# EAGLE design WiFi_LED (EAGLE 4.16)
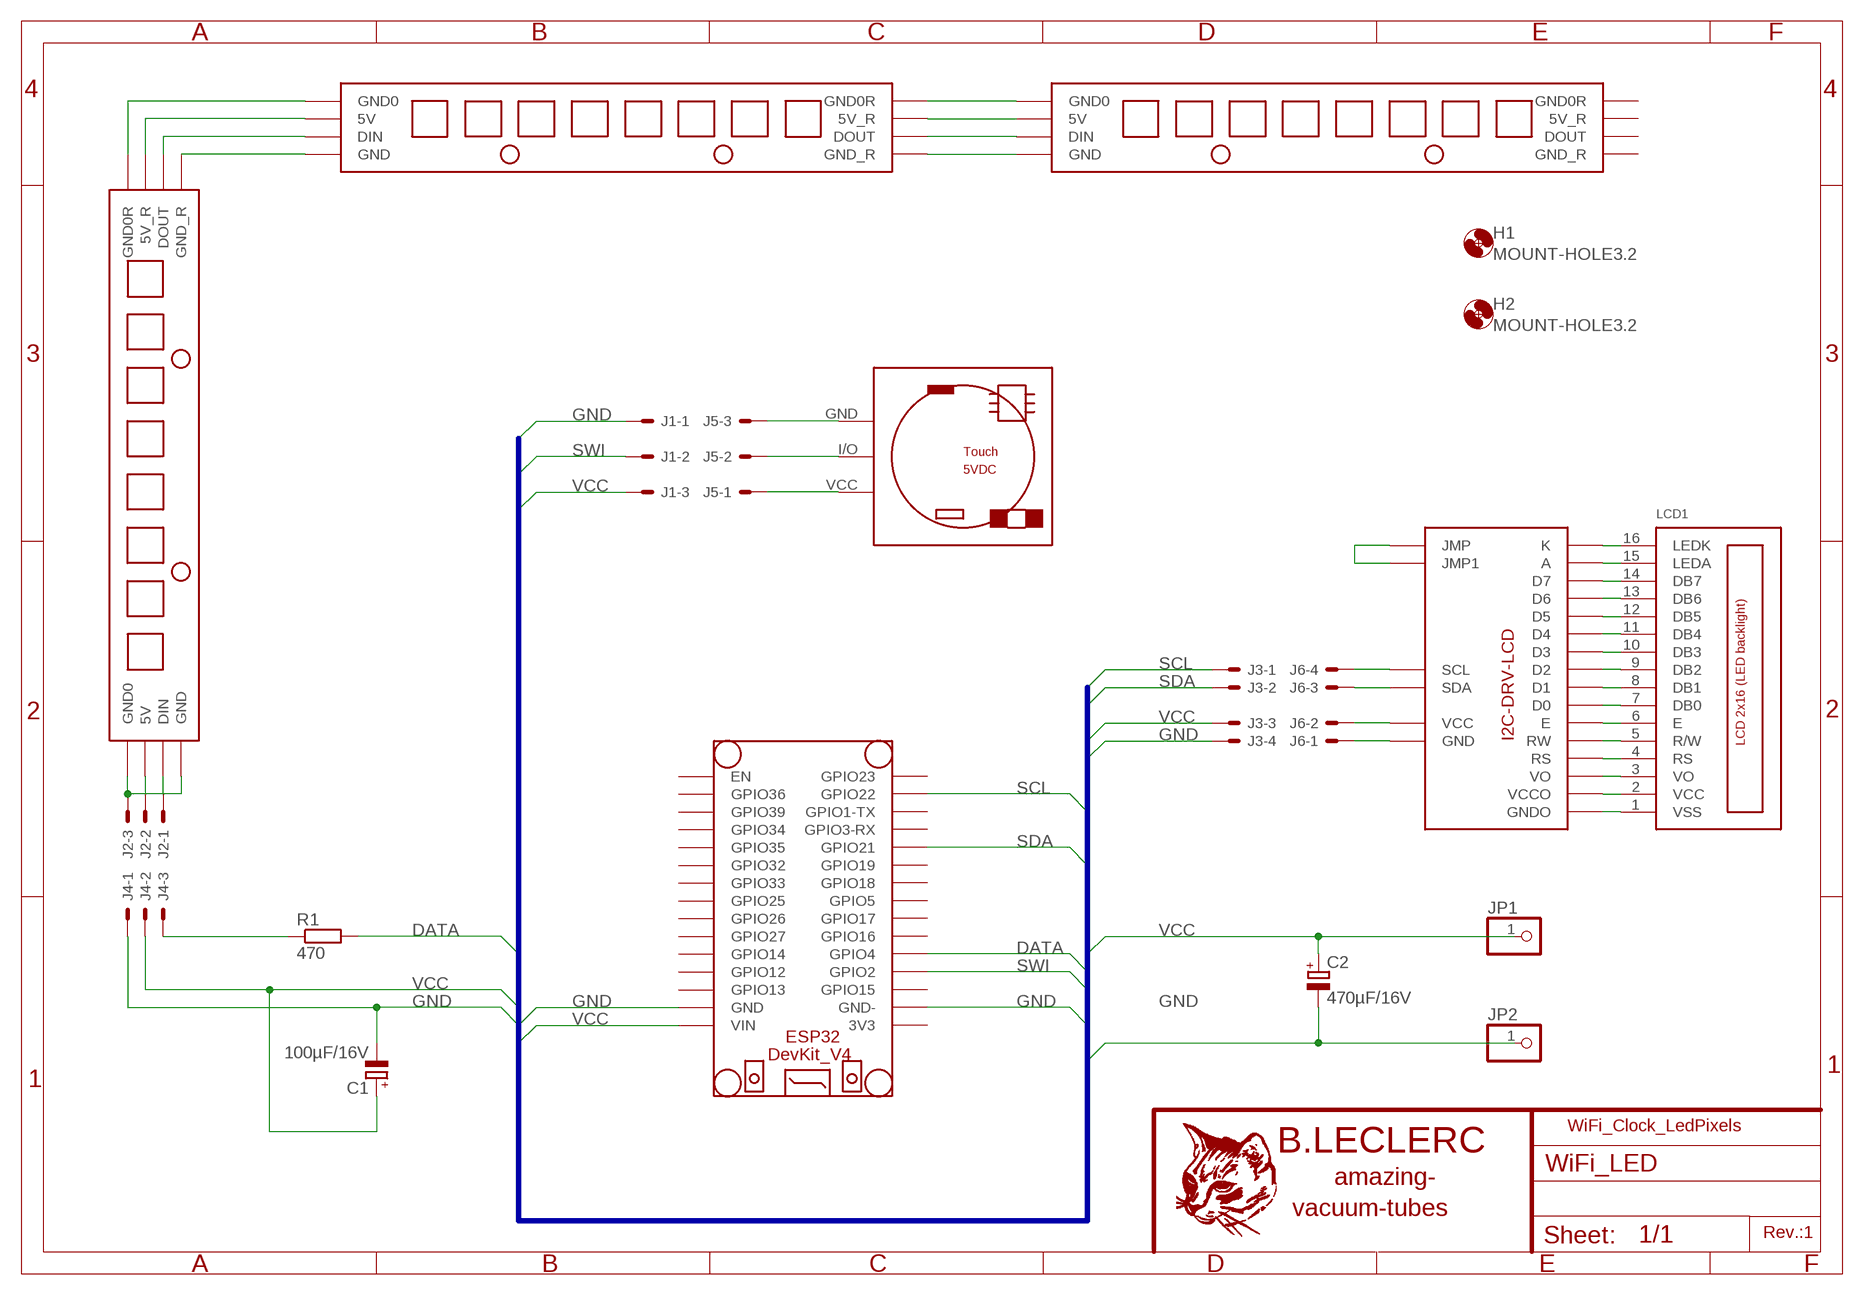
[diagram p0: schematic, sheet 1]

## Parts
C1  100µF/16V  CPOL-EUE2.5-7  [E2,5-7]
C2  470µF/16V  CPOL-EUE2.5-7  [E2,5-7]
H1  MOUNT-HOLE3.2  [3,2]
H2  MOUNT-HOLE3.2  [3,2]
J1  22-27-2031-03  [6410-03]
J2  22-27-2031-03  [6410-03]
J3  22-27-2041-04  [6410-04]
J4  22-27-2031-03  [6410-03]
J5  22-27-2031-03  [6410-03]
J6  22-27-2041-04  [6410-04]
JP1  PINHD-1X1  [1X01]
JP2  PINHD-1X1  [1X01]
LCD1  LCD_2X16_SIL  [HY-1602F]
LL1  8_LED_LINE_PANEL  [8_LED_LINE_PANEL]
LL2  8_LED_LINE_PANEL  [8_LED_LINE_PANEL]
LL3  8_LED_LINE_PANEL  [8_LED_LINE_PANEL]
R1  470  R-EU_M1206  [M1206]
U$2  ESP32  [ESP32]
U$3  I2C-DRV-LCD  [I2C_DRV_LCD]
U$6  TOUCH-BUTTON  [TOUCH-BUTTON]

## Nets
DATA: J4.3 R1.1 R1.2 U$2.GPIO4
GND: C1.- C2.- J1.1 J3.4 J4.1 JP2.1 U$2.GND U$2.GND-
N$1: LCD1.16(LEDK) U$3.K
N$2: LCD1.15(LEDA) U$3.A
N$3: LCD1.14(DB7) U$3.D7
N$4: LCD1.13(DB6) U$3.D6
N$5: LCD1.12(DB5) U$3.D5
N$6: LCD1.11(DB4) U$3.D4
N$7: LCD1.10(DB3) U$3.D3
N$8: LCD1.9(DB2) U$3.D2
N$9: LCD1.8(DB1) U$3.D1
N$10: LCD1.7(DB0) U$3.D0
N$11: LCD1.6(E) U$3.E
N$12: LCD1.5(R/W) U$3.RW
N$13: LCD1.4(RS) U$3.RS
N$14: LCD1.3(VO) U$3.VO
N$15: LCD1.2(VCC) U$3.VCCO
N$16: LCD1.1(VSS) U$3.GNDO
N$17: U$3.P$21(JMP) U$3.P$22(JMP1)
N$18: LL1.GND0 LL2.GND0R
N$19: LL1.5V LL2.5VR(5V_R)
N$20: LL1.DIN LL2.DOUT
N$21: LL1.GND LL2.GNDR(GND_R)
N$22: LL2.GND0 LL3.GND0R
N$23: LL2.5V LL3.5VR(5V_R)
N$24: LL2.DIN LL3.DOUT
N$25: LL2.GND LL3.GNDR(GND_R)
N$26: J5.3 U$6.GND
N$27: J5.2 U$6.I/O
N$28: J5.1 U$6.VCC
N$29: J6.4 U$3.SCL
N$30: J6.3 U$3.SDA
N$31: J6.2 U$3.VCC
N$32: J6.1 U$3.GND
N$33: J2.3 LL3.GND LL3.GND0
N$34: J2.2 LL3.5V
N$35: J2.1 LL3.DIN
SCL: J3.1 U$2.GPIO22
SDA: J3.2 U$2.GPIO21
SWI: J1.2 U$2.GPIO2
VCC: C1.+ C2.+ J1.3 J3.3 J4.2 JP1.1 U$2.VIN
Unconnected: LL1.DOUT U$2.EN U$2.GPIO1-TX U$2.GPIO3-RX U$2.GPIO5 U$2.GPIO12 U$2.GPIO13 U$2.GPIO14 U$2.GPIO15 U$2.GPIO16 U$2.GPIO17 U$2.GPIO18 U$2.GPIO19 U$2.GPIO23 U$2.GPIO25 U$2.GPIO26 U$2.GPIO27 U$2.GPIO32 U$2.GPIO33 U$2.GPIO34 U$2.GPIO35 U$2.GPIO36 U$2.GPIO39

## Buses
B$1

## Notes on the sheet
- WiFi_Clock_LedPixels
- Rev.:1

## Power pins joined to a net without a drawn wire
3V3: U$2.3V3
5V_R: LL1.5VR(5V_R)
GND0R: LL1.GND0R
GND_R: LL1.GNDR(GND_R)

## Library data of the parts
C1 C2 = rcl:CPOL-EU: POLARIZED CAPACITOR, European symbol
H1 H2 = holes:MOUNT-HOLE: MOUNTING HOLE with drill center marker
J1 J2 J4 J5 = con-molex:22-?-03: CONNECTOR wire to board 2.54 mm (.1 inch) pitch header
J3 J6 = con-molex:22-?-04: CONNECTOR wire to board 2.54 mm (.1 inch) pitch header
JP1 JP2 = pinhead:PINHD-1X1: PIN HEADER
LCD1 = lcd_2x16_led_backlight:LCD_2X16_SIL
LL1-LL3 = Arduino:8_LED_LINE_PANEL
R1 = rcl:R-EU_: RESISTOR, European symbol
U$2 = Arduino:ESP32
U$3 = Arduino:I2C-DRV-LCD
U$6 = Arduino:TOUCH-BUTTON

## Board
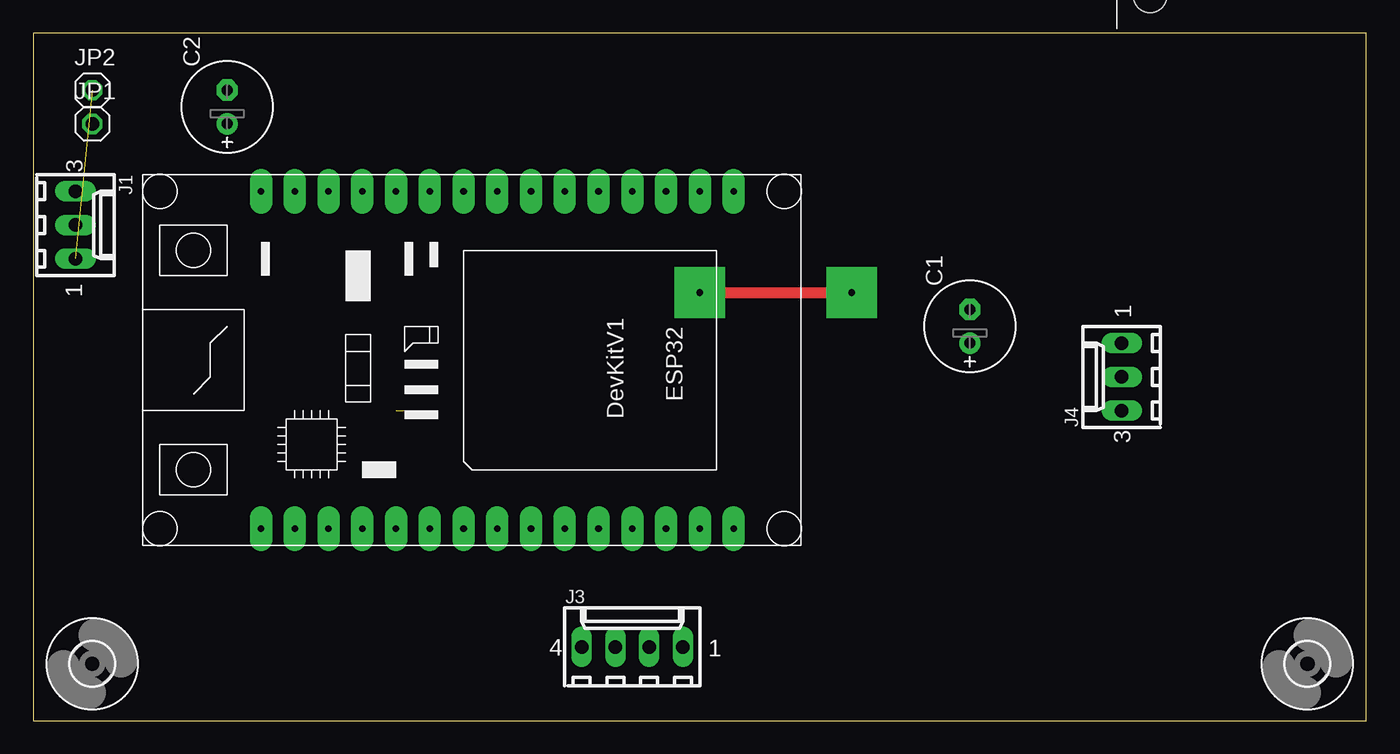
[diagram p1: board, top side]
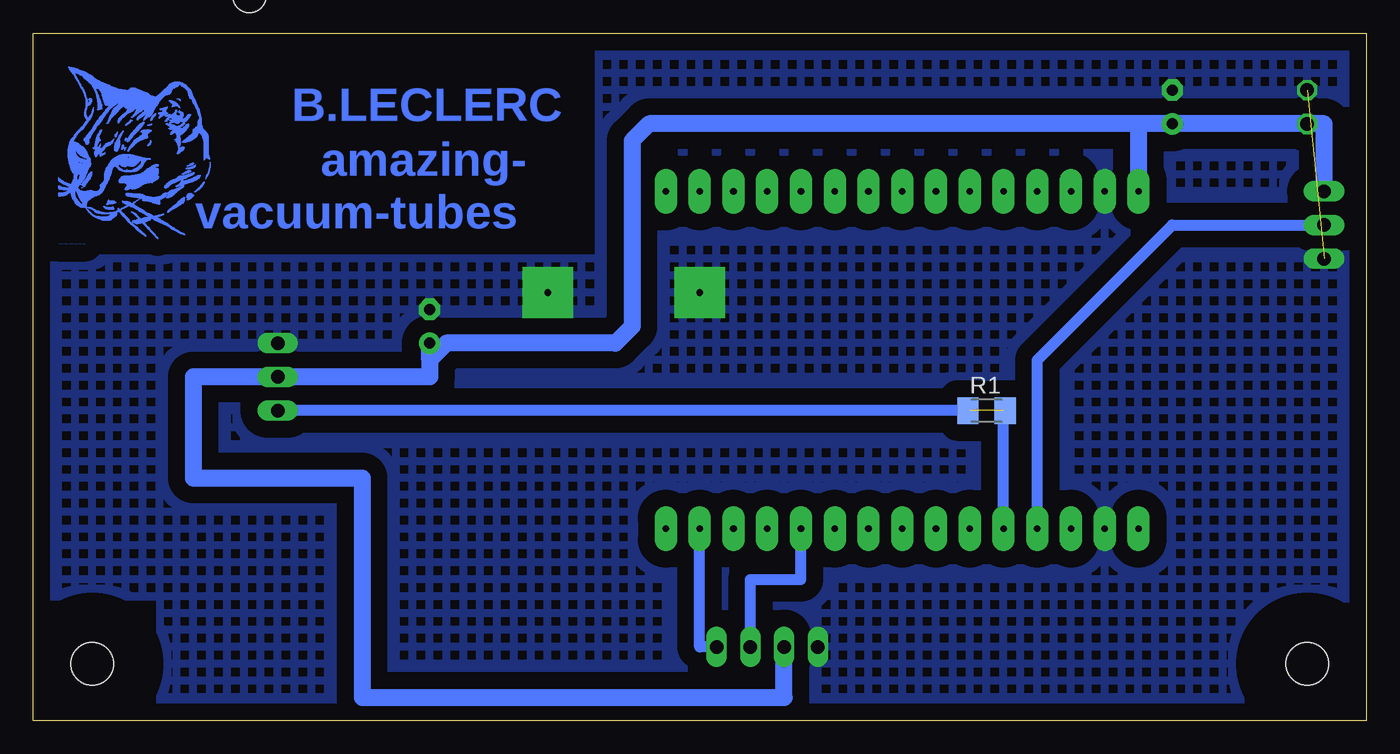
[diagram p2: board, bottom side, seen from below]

Size 100.31 x 51.74 mm. Coordinates in mm from the lower left corner, seen from the top.
Outline: 0,0 100.31,0 100.31,51.74 0,51.74 0,0
Copper layers (1*16): Top 0.035mm / dielectric 1.5mm / Bottom 0.035mm
Design rules "default": minimum track width 10mil, minimum drill 24mil, track to track 8mil, track to pad 8mil, pad to pad 8mil, via to via 8mil, smd to smd 8mil, copper to edge 40mil, drill to drill 8mil, minimum pad ring 10mil, minimum via ring 8mil, stop-mask expansion 4mil, vias tented up to drill 0mil, thermal gap 10mil

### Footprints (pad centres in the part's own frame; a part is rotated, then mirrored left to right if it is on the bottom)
E2,5-7 = drill 0.813 pad 1.6 round: + -1.27,0 | drill 0.813 pad 1.6 octagon: - 1.27,0
3,2 = hole 3.2: 0,0
6410-03 = drill 1.016 long: 1 2.54,0; 2 0,0; 3 -2.54,0
6410-04 = drill 1.016 long: 1 3.81,0; 2 1.27,0; 3 -1.27,0; 4 -3.81,0
1X01 = drill 1.016 octagon: 1 0,0
HY-1602F = drill 1 pad 1.93 long: 1 2.54,0; 2 5.08,0; 3 7.62,0; 4 10.16,0; 5 12.7,0; 6 15.24,0; 7 17.78,0; 8 20.32,0; 9 22.86,0; 10 25.4,0; 11 27.94,0; 12 30.48,0; 13 33.02,0; 14 35.56,0; 15 38.1,0; 16 40.64,0 | hole 2.5: -2.96,0; 72.04,0; -2.96,-31; 72.04,-31
8_LED_LINE_PANEL = drill 0.5 pad 1.93 offset: 5V -25.4,1.27; 5VR 25.4,1.27; DIN -25.4,-1.27; DOUT 25.4,-1.27; GND -25.4,-3.81; GND0 -25.4,3.81; GND0R 25.4,3.81; GNDR 25.4,-3.81
M1206 = smd 1.6 x 2: 1 -1.4,0; 2 1.4,0
ESP32 = drill 0.5 pad 1.676 long: 3V3 12.7,-15.24; EN -12.7,20.32; GND -12.7,-12.7; GND- 12.7,-12.7; GPIO1-TX 12.7,15.24; GPIO2 12.7,-7.62; GPIO3-RX 12.7,12.7; GPIO4 12.7,-5.08; GPIO5 12.7,2.54; GPIO12 -12.7,-7.62; GPIO13 -12.7,-10.16; GPIO14 -12.7,-5.08; GPIO15 12.7,-10.16; GPIO16 12.7,-2.54; GPIO17 12.7,0; GPIO18 12.7,5.08; GPIO19 12.7,7.62; GPIO21 12.7,10.16; GPIO22 12.7,17.78; GPIO23 12.7,20.32; GPIO25 -12.7,2.54; GPIO26 -12.7,0; GPIO27 -12.7,-2.54; GPIO32 -12.7,7.62; GPIO33 -12.7,5.08; GPIO34 -12.7,12.7; GPIO35 -12.7,10.16; GPIO36 -12.7,17.78; GPIO39 -12.7,15.24; VIN -12.7,-15.24
I2C_DRV_LCD = drill 0.5 pad 1.93 long: A 0,16.51; D0 0,-3.81; D1 0,-1.27; D2 0,1.27; D3 0,3.81; D4 0,6.35; D5 0,8.89; D6 0,11.43; D7 0,13.97; E 0,-6.35; GND -3.81,-19.05; GNDO 0,-19.05; K 0,19.05; P$21 -7.62,19.05; P$22 -5.08,19.05; RS 0,-11.43; RW 0,-8.89; SCL -11.43,-19.05; SDA -8.89,-19.05; VCC -6.35,-19.05; VCCO 0,-16.51; VO 0,-13.97
TOUCH-BUTTON = drill 0.5 pad 1.93 square: GND 0,2.54 | drill 0.5 pad 1.93 octagon: I/O 0,0; VCC 0,-2.54

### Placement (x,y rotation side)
C1  70.48,29.68 90 top
C2  14.6,46.19 90 top
H1  95.88,4.28 0 top
H2  4.44,4.28 0 top
J1  3.17,37.3 270 top
J2  not placed on the board
J3  45.08,5.55 0 top
J4  81.91,25.87 90 top
J5  not placed on the board
J6  not placed on the board
JP1  4.44,44.92 0 top
JP2  4.44,47.46 0 top
LCD1  86.99,85.56 0 top
LL1  not placed on the board
LL2  not placed on the board
LL3  not placed on the board
R1  28.57,23.33 0 bottom
U$2  32.38,27.14 270 top
U$3  not placed on the board
U$4  [CHAT1]  98.42,36.03 0 bottom
U$6  not placed on the board

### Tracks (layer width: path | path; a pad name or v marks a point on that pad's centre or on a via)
DATA  (1 unrouted)
  Bottom 0.813: R1.2 27.3,23.33 U$2.GPIO4 | 29.84,23.33 R1.1 J4.3
GND  (via drill 0.5 pad 3.81)  (1 unrouted)
  Top 0.813: v50.16,32.22 v61.59,32.22
  pour Bottom (isolate 1.27, no thermals, hatched): 0.63,51.27 57.78,51.27 57.78,50 57.78,34.76 99.69,34.76 99.69,9.36 78.1,9.36 90.8,9.36 90.8,0.47 0.63,0.47 0.63,10.63
N$1  (1 unrouted)
N$2  (1 unrouted)
N$3  (1 unrouted)
N$4  (1 unrouted)
N$5  (1 unrouted)
N$6  (1 unrouted)
N$7  (1 unrouted)
N$8  (1 unrouted)
N$9  (1 unrouted)
N$10  (1 unrouted)
N$11  (1 unrouted)
N$12  (1 unrouted)
N$13  (1 unrouted)
N$14  (1 unrouted)
N$15  (1 unrouted)
N$16  (1 unrouted)
N$17  (1 unrouted)
N$18  (1 unrouted)
N$19  (1 unrouted)
N$20  (1 unrouted)
N$21  (1 unrouted)
N$22  (1 unrouted)
N$23  (1 unrouted)
N$24  (1 unrouted)
N$25  (1 unrouted)
N$26  (1 unrouted)
N$27  (1 unrouted)
N$28  (1 unrouted)
N$29  (1 unrouted)
N$30  (1 unrouted)
N$31  (1 unrouted)
N$32  (1 unrouted)
N$33  (2 unrouted)
N$34  (1 unrouted)
N$35  (1 unrouted)
SCL
  Bottom 0.813: U$2.GPIO22 50.16,5.55 J3.1
SDA
  Bottom 0.813: U$2.GPIO21 42.54,10.63 46.35,10.63 J3.2
SWI
  Bottom 0.813: J1.2 14.6,37.3 24.76,27.14 U$2.GPIO2
VCC
  Bottom 1.27: J1.3 3.17,44.92 JP1.1 C2.+ 17.14,44.92 | J3.3 43.81,1.74 75.56,1.74 75.56,18.25 88.26,18.25 88.26,25.87 J4.2 70.48,25.87 70.48,27.14 | 70.48,27.14 C1.+ | 17.14,44.92 U$2.VIN | 17.14,44.92 53.97,44.92 55.24,43.65 55.24,29.68 56.51,28.41 69.21,28.41 70.48,27.14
